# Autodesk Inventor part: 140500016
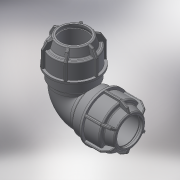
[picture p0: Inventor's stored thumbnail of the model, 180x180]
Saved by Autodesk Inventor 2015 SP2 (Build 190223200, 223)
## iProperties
Created: 2017-08
Part Number: 140500016
Material: Generic
Description: PLASSON L.14 90° ELBOW (SILVER) 16-16
Document SubType Name: Modeling
Designer: KIM
Density: 1 g/cm^3
Appearance: Default
Author: KIM
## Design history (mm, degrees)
derived "140500.ipt"
feature "Solid1::140500.ipt"
tag "TaggingFeature1"
body "Solid1"
other parameters: "d1" = 16, "d2" = 51, "d4" = 15 deg, "d5" = 33.66, "d6" = 11.1078, "d10" = 39, "d16" = 16.32, "d17" = 2.55, "d22" = 25.6, "d24" = 2.55, "d25" = 35.1, "d26" = 29.25, "d27" = 2.55, "d28" = 135 deg, "d29" = 1.53, "d31" = 0.8, "d46" = 150 deg, "d49" = 1.95, "d50" = 0, "d58" = 0.48, "d61" = 360 deg, "d63" = 14.4, "d80" = 23.04, "d81" = 1.28, "d84" = 2.55, "d112" = 64, "d113" = 2.56, "d115" = 90 deg, "d_" = 16, "E_" = 39, "A_" = 64, "l_" = 51
